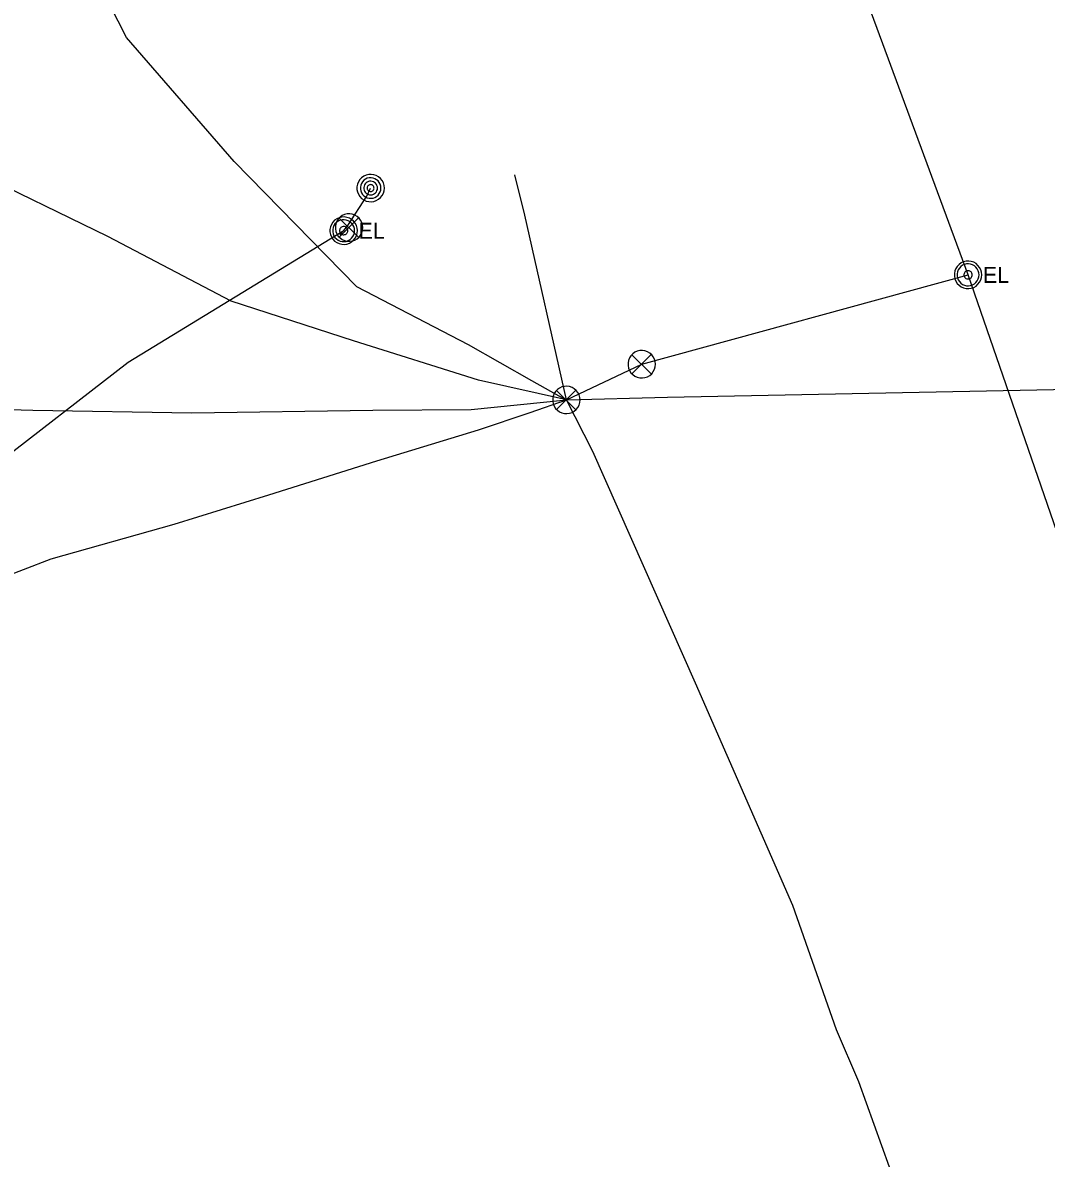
# Model space of a CAD drawing. Extents: x 600849 to 606371, y 330010 to 403088.
# Drawn here: x 603787.2 to 604033, y 349495.8 to 349768.6 of the extents above; entities that cross this region are included whole.
import ezdxf

# ---------------------------------------------------------------- set-up
doc = ezdxf.new("R2010")
doc.units = 0
for name, color, linetype in [('E_FTMS', 7, 'Continuous'), ('E_FTMS_Conduit', 7, 'Continuous'), ('E_LTG_CID', 7, 'Continuous'), ('E_MISCPROP', 7, 'Continuous'), ('E_SIG', 7, 'Continuous'), ('E_UTL_E', 7, 'Continuous'), ('E_UTL_T_UG', 7, 'Continuous')]:
    doc.layers.add(name, color=color, linetype=linetype)

msp = doc.modelspace()

# ---------------------------------------------------------------- linework, layer by layer
at = {"layer": 'E_FTMS'}
for points in [[(603868.86, 349719.43), (603868.8, 349720.05), (603868.62, 349720.66), (603868.33, 349721.21), (603867.95, 349721.71), (603867.47, 349722.12), (603866.93, 349722.43), (603866.33, 349722.64), (603865.71, 349722.73), (603865.09, 349722.7), (603864.48, 349722.55), (603863.91, 349722.29), (603863.4, 349721.92), (603862.96, 349721.47), (603862.62, 349720.94), (603862.39, 349720.36), (603862.27, 349719.74), (603862.27, 349719.12), (603862.39, 349718.5), (603862.62, 349717.92), (603862.96, 349717.39), (603863.4, 349716.94), (603863.91, 349716.57), (603864.48, 349716.31), (603865.09, 349716.16), (603865.71, 349716.13), (603866.33, 349716.22), (603866.93, 349716.43), (603867.47, 349716.74), (603867.95, 349717.15), (603868.33, 349717.65), (603868.62, 349718.2), (603868.8, 349718.81), (603868.86, 349719.43)], [(603867.82, 349721.76), (603863.21, 349717.11)], [(603863.21, 349721.72), (603867.86, 349717.06)], [(603921.05, 349678.01), (603920.99, 349678.63), (603920.81, 349679.23), (603920.52, 349679.79), (603920.14, 349680.29), (603919.66, 349680.7), (603919.12, 349681.01), (603918.53, 349681.21), (603917.9, 349681.3), (603917.28, 349681.27), (603916.67, 349681.13), (603916.1, 349680.87), (603915.59, 349680.5), (603915.15, 349680.05), (603914.81, 349679.52), (603914.58, 349678.94), (603914.46, 349678.32), (603914.46, 349677.69), (603914.58, 349677.08), (603914.81, 349676.5), (603915.15, 349675.97), (603915.59, 349675.51), (603916.1, 349675.15), (603916.67, 349674.89), (603917.28, 349674.74), (603917.9, 349674.71), (603918.53, 349674.8), (603919.12, 349675.01), (603919.66, 349675.32), (603920.14, 349675.73), (603920.52, 349676.22), (603920.81, 349676.78), (603920.99, 349677.38), (603921.05, 349678.01)], [(603920.01, 349680.34), (603915.4, 349675.69)], [(603915.4, 349680.29), (603920.05, 349675.64)]]:
    msp.add_lwpolyline(points, dxfattribs=at)
at = {"layer": 'E_FTMS_Conduit'}
for points in [[(603917.75, 349678.01), (603916.03, 349678.92), (603909.47, 349682.62), (603894.24, 349691.26), (603867.44, 349705.17), (603837.96, 349735.31), (603812.11, 349765.12), (603792, 349804.62)], [(603982.63, 349526.67), (603972.12, 349556.51), (603948.77, 349609.95), (603924.1, 349665.61), (603917.75, 349678.01), (603907.79, 349722.38), (603905.34, 349732.1)], [(603863.31, 349717.64), (603864.3, 349718.69), (603865.25, 349719.95), (603869.81, 349726.99), (603870.73, 349728.92)], [(603744.86, 349619.98), (603745.63, 349621.39), (603766.11, 349640.68), (603779.36, 349661.48), (603812.47, 349687.08), (603864.3, 349718.69)], [(603754.02, 349624.44), (603794, 349639.8), (603823.54, 349648.17), (603846.28, 349655.2), (603872.25, 349663.34), (603896.64, 349670.84), (603909.04, 349674.97), (603917.75, 349678.01)], [(604122.74, 348988.04), (604108.56, 349049.67), (604100.88, 349081.84), (604090.92, 349138.93), (604079.09, 349196.91), (604056.03, 349276.86), (604043.16, 349350.52), (604043.52, 349350.57), (604038.65, 349379.99), (604027.8, 349419.58), (604014.43, 349447.39), (603999.06, 349483.4), (603987.98, 349514.15), (603982.63, 349526.67)]]:
    msp.add_lwpolyline(points, dxfattribs=at)
at = {"layer": 'E_LTG_CID'}
for points in [[(604318.05, 348339.7), (604287.36, 348606.91), (604242.16, 348872.6), (604188.57, 349120.13), (604125.01, 349362.84), (604050.82, 349602.08), (604014.23, 349708.06), (603966.43, 349837.54), (603869.82, 350091.09), (603838.85, 350172.22), (603784.41, 350315.72), (603699.29, 350539.43), (603613.87, 350764.2), (603510.34, 351036.54), (603442.84, 351213.06), (603357.76, 351436.96)], [(603917.75, 349678.01), (603896.67, 349682.78), (603866.61, 349692.2), (603837.24, 349701.77), (603807.63, 349717.3), (603774.3, 349733.47), (603748.77, 349742.3), (603723.01, 349748.61), (603703.89, 349751.51), (603692.25, 349754.99), (603690.94, 349755.27)], [(603935.86, 349686.59), (604014.23, 349708.06)], [(603917.75, 349678.01), (603935.86, 349686.59)]]:
    msp.add_lwpolyline(points, dxfattribs=at)
at = {"layer": 'E_MISCPROP'}
for points in [[(603874.03, 349728.92), (603873.97, 349729.54), (603873.79, 349730.14), (603873.5, 349730.7), (603873.11, 349731.19), (603872.64, 349731.61), (603872.1, 349731.92), (603871.5, 349732.12), (603870.88, 349732.21), (603870.26, 349732.18), (603869.65, 349732.04), (603869.08, 349731.78), (603868.56, 349731.41), (603868.13, 349730.96), (603867.79, 349730.43), (603867.56, 349729.85), (603867.44, 349729.23), (603867.44, 349728.6), (603867.56, 349727.99), (603867.79, 349727.41), (603868.13, 349726.88), (603868.56, 349726.42), (603869.08, 349726.06), (603869.65, 349725.8), (603870.26, 349725.65), (603870.88, 349725.62), (603871.5, 349725.71), (603872.1, 349725.92), (603872.64, 349726.23), (603873.11, 349726.64), (603873.5, 349727.13), (603873.79, 349727.69), (603873.97, 349728.29), (603874.03, 349728.92)], [(603873.2, 349728.92), (603873.16, 349729.39), (603873.02, 349729.84), (603872.81, 349730.26), (603872.52, 349730.63), (603872.16, 349730.93), (603871.75, 349731.17), (603871.31, 349731.32), (603870.84, 349731.39), (603870.37, 349731.37), (603869.92, 349731.26), (603869.49, 349731.06), (603869.1, 349730.79), (603868.78, 349730.45), (603868.53, 349730.05), (603868.35, 349729.61), (603868.26, 349729.15), (603868.26, 349728.68), (603868.35, 349728.22), (603868.53, 349727.78), (603868.78, 349727.39), (603869.1, 349727.05), (603869.49, 349726.77), (603869.92, 349726.58), (603870.37, 349726.47), (603870.84, 349726.45), (603871.31, 349726.51), (603871.75, 349726.67), (603872.16, 349726.9), (603872.52, 349727.21), (603872.81, 349727.58), (603873.02, 349728), (603873.16, 349728.45), (603873.2, 349728.92)], [(603872.38, 349728.92), (603872.35, 349729.23), (603872.26, 349729.53), (603872.11, 349729.81), (603871.92, 349730.06), (603871.68, 349730.26), (603871.41, 349730.42), (603871.11, 349730.52), (603870.8, 349730.57), (603870.49, 349730.55), (603870.19, 349730.48), (603869.9, 349730.35), (603869.65, 349730.16), (603869.43, 349729.94), (603869.26, 349729.67), (603869.14, 349729.38), (603869.08, 349729.07), (603869.08, 349728.76), (603869.14, 349728.45), (603869.26, 349728.16), (603869.43, 349727.9), (603869.65, 349727.67), (603869.9, 349727.49), (603870.19, 349727.36), (603870.49, 349727.28), (603870.8, 349727.27), (603871.11, 349727.31), (603871.41, 349727.42), (603871.68, 349727.57), (603871.92, 349727.78), (603872.11, 349728.03), (603872.26, 349728.3), (603872.35, 349728.61), (603872.38, 349728.92)], [(603871.55, 349728.92), (603871.54, 349729.07), (603871.49, 349729.22), (603871.42, 349729.36), (603871.32, 349729.49), (603871.2, 349729.59), (603871.07, 349729.67), (603870.92, 349729.72), (603870.76, 349729.74), (603870.61, 349729.73), (603870.46, 349729.7), (603870.31, 349729.63), (603870.19, 349729.54), (603870.08, 349729.43), (603869.99, 349729.3), (603869.93, 349729.15), (603869.9, 349729), (603869.9, 349728.84), (603869.93, 349728.68), (603869.99, 349728.54), (603870.08, 349728.41), (603870.19, 349728.29), (603870.31, 349728.2), (603870.46, 349728.14), (603870.61, 349728.1), (603870.76, 349728.09), (603870.92, 349728.12), (603871.07, 349728.17), (603871.2, 349728.25), (603871.32, 349728.35), (603871.42, 349728.47), (603871.49, 349728.61), (603871.54, 349728.76), (603871.55, 349728.92)]]:
    msp.add_lwpolyline(points, dxfattribs=at)
at = {"layer": 'E_SIG'}
for points in [[(603939.16, 349686.59), (603939.1, 349687.21), (603938.92, 349687.81), (603938.63, 349688.37), (603938.24, 349688.87), (603937.77, 349689.28), (603937.23, 349689.59), (603936.63, 349689.79), (603936.01, 349689.88), (603935.39, 349689.85), (603934.78, 349689.71), (603934.21, 349689.45), (603933.7, 349689.08), (603933.26, 349688.63), (603932.92, 349688.1), (603932.69, 349687.52), (603932.57, 349686.9), (603932.57, 349686.27), (603932.69, 349685.66), (603932.92, 349685.08), (603933.26, 349684.55), (603933.7, 349684.09), (603934.21, 349683.73), (603934.78, 349683.47), (603935.39, 349683.32), (603936.01, 349683.29), (603936.63, 349683.38), (603937.23, 349683.59), (603937.77, 349683.9), (603938.24, 349684.31), (603938.63, 349684.8), (603938.92, 349685.36), (603939.1, 349685.96), (603939.16, 349686.59)], [(603938.12, 349688.92), (603933.51, 349684.27)], [(603933.51, 349688.87), (603938.16, 349684.22)]]:
    msp.add_lwpolyline(points, dxfattribs=at)
at = {"layer": 'E_UTL_E'}
for points in [[(603867.55, 349718.68), (603867.49, 349719.3), (603867.31, 349719.9), (603867.02, 349720.46), (603866.64, 349720.95), (603866.16, 349721.37), (603865.62, 349721.68), (603865.02, 349721.88), (603864.4, 349721.97), (603863.78, 349721.94), (603863.17, 349721.8), (603862.6, 349721.54), (603862.09, 349721.17), (603861.65, 349720.72), (603861.31, 349720.19), (603861.08, 349719.61), (603860.96, 349718.99), (603860.96, 349718.36), (603861.08, 349717.75), (603861.31, 349717.17), (603861.65, 349716.64), (603862.09, 349716.18), (603862.6, 349715.82), (603863.17, 349715.56), (603863.78, 349715.41), (603864.4, 349715.38), (603865.02, 349715.47), (603865.62, 349715.68), (603866.16, 349715.99), (603866.64, 349716.4), (603867.02, 349716.89), (603867.31, 349717.45), (603867.49, 349718.05), (603867.55, 349718.68)], [(603867.55, 349718.68), (603867.49, 349719.3), (603867.31, 349719.9), (603867.02, 349720.46), (603866.64, 349720.95), (603866.16, 349721.37), (603865.62, 349721.68), (603865.02, 349721.88), (603864.4, 349721.97), (603863.78, 349721.94), (603863.17, 349721.8), (603862.6, 349721.54), (603862.09, 349721.17), (603861.65, 349720.72), (603861.31, 349720.19), (603861.08, 349719.61), (603860.96, 349718.99), (603860.96, 349718.36), (603861.08, 349717.75), (603861.31, 349717.17), (603861.65, 349716.64), (603862.09, 349716.18), (603862.6, 349715.82), (603863.17, 349715.56), (603863.78, 349715.41), (603864.4, 349715.38), (603865.02, 349715.47), (603865.62, 349715.68), (603866.16, 349715.99), (603866.64, 349716.4), (603867.02, 349716.89), (603867.31, 349717.45), (603867.49, 349718.05), (603867.55, 349718.68)], [(603866.89, 349718.68), (603866.84, 349719.18), (603866.7, 349719.66), (603866.47, 349720.1), (603866.16, 349720.5), (603865.78, 349720.83), (603865.34, 349721.08), (603864.87, 349721.24), (603864.37, 349721.31), (603863.87, 349721.29), (603863.38, 349721.17), (603862.93, 349720.96), (603862.52, 349720.67), (603862.17, 349720.31), (603861.9, 349719.89), (603861.71, 349719.42), (603861.62, 349718.93), (603861.62, 349718.43), (603861.71, 349717.93), (603861.9, 349717.47), (603862.17, 349717.05), (603862.52, 349716.68), (603862.93, 349716.39), (603863.38, 349716.18), (603863.87, 349716.06), (603864.37, 349716.04), (603864.87, 349716.11), (603865.34, 349716.28), (603865.78, 349716.53), (603866.16, 349716.86), (603866.47, 349717.25), (603866.7, 349717.7), (603866.84, 349718.18), (603866.89, 349718.68)], [(603866.89, 349718.68), (603866.84, 349719.18), (603866.7, 349719.66), (603866.47, 349720.1), (603866.16, 349720.5), (603865.78, 349720.83), (603865.34, 349721.08), (603864.87, 349721.24), (603864.37, 349721.31), (603863.87, 349721.29), (603863.38, 349721.17), (603862.93, 349720.96), (603862.52, 349720.67), (603862.17, 349720.31), (603861.9, 349719.89), (603861.71, 349719.42), (603861.62, 349718.93), (603861.62, 349718.43), (603861.71, 349717.93), (603861.9, 349717.47), (603862.17, 349717.05), (603862.52, 349716.68), (603862.93, 349716.39), (603863.38, 349716.18), (603863.87, 349716.06), (603864.37, 349716.04), (603864.87, 349716.11), (603865.34, 349716.28), (603865.78, 349716.53), (603866.16, 349716.86), (603866.47, 349717.25), (603866.7, 349717.7), (603866.84, 349718.18), (603866.89, 349718.68)], [(603865.24, 349718.68), (603865.22, 349718.87), (603865.17, 349719.05), (603865.08, 349719.21), (603864.96, 349719.36), (603864.82, 349719.48), (603864.66, 349719.58), (603864.48, 349719.64), (603864.29, 349719.67), (603864.11, 349719.66), (603863.92, 349719.61), (603863.75, 349719.54), (603863.6, 349719.43), (603863.47, 349719.29), (603863.37, 349719.13), (603863.3, 349718.96), (603863.26, 349718.77), (603863.26, 349718.58), (603863.3, 349718.4), (603863.37, 349718.22), (603863.47, 349718.07), (603863.6, 349717.93), (603863.75, 349717.82), (603863.92, 349717.74), (603864.11, 349717.7), (603864.29, 349717.69), (603864.48, 349717.72), (603864.66, 349717.78), (603864.82, 349717.87), (603864.96, 349717.99), (603865.08, 349718.14), (603865.17, 349718.31), (603865.22, 349718.49), (603865.24, 349718.68)], [(603865.24, 349718.68), (603865.22, 349718.87), (603865.17, 349719.05), (603865.08, 349719.21), (603864.96, 349719.36), (603864.82, 349719.48), (603864.66, 349719.58), (603864.48, 349719.64), (603864.29, 349719.67), (603864.11, 349719.66), (603863.92, 349719.61), (603863.75, 349719.54), (603863.6, 349719.43), (603863.47, 349719.29), (603863.37, 349719.13), (603863.3, 349718.96), (603863.26, 349718.77), (603863.26, 349718.58), (603863.3, 349718.4), (603863.37, 349718.22), (603863.47, 349718.07), (603863.6, 349717.93), (603863.75, 349717.82), (603863.92, 349717.74), (603864.11, 349717.7), (603864.29, 349717.69), (603864.48, 349717.72), (603864.66, 349717.78), (603864.82, 349717.87), (603864.96, 349717.99), (603865.08, 349718.14), (603865.17, 349718.31), (603865.22, 349718.49), (603865.24, 349718.68)], [(604017.53, 349708.06), (604017.47, 349708.69), (604017.3, 349709.29), (604017.01, 349709.85), (604016.62, 349710.34), (604016.15, 349710.75), (604015.6, 349711.07), (604015.01, 349711.27), (604014.39, 349711.36), (604013.76, 349711.33), (604013.15, 349711.18), (604012.58, 349710.92), (604012.07, 349710.56), (604011.64, 349710.1), (604011.3, 349709.58), (604011.07, 349708.99), (604010.95, 349708.38), (604010.95, 349707.75), (604011.07, 349707.13), (604011.3, 349706.55), (604011.64, 349706.02), (604012.07, 349705.57), (604012.58, 349705.21), (604013.15, 349704.95), (604013.76, 349704.8), (604014.39, 349704.77), (604015.01, 349704.86), (604015.6, 349705.06), (604016.15, 349705.38), (604016.62, 349705.79), (604017.01, 349706.28), (604017.3, 349706.84), (604017.47, 349707.44), (604017.53, 349708.06)], [(604017.53, 349708.06), (604017.47, 349708.69), (604017.3, 349709.29), (604017.01, 349709.85), (604016.62, 349710.34), (604016.15, 349710.75), (604015.6, 349711.07), (604015.01, 349711.27), (604014.39, 349711.36), (604013.76, 349711.33), (604013.15, 349711.18), (604012.58, 349710.92), (604012.07, 349710.56), (604011.64, 349710.1), (604011.3, 349709.58), (604011.07, 349708.99), (604010.95, 349708.38), (604010.95, 349707.75), (604011.07, 349707.13), (604011.3, 349706.55), (604011.64, 349706.02), (604012.07, 349705.57), (604012.58, 349705.21), (604013.15, 349704.95), (604013.76, 349704.8), (604014.39, 349704.77), (604015.01, 349704.86), (604015.6, 349705.06), (604016.15, 349705.38), (604016.62, 349705.79), (604017.01, 349706.28), (604017.3, 349706.84), (604017.47, 349707.44), (604017.53, 349708.06)], [(604016.87, 349708.06), (604016.82, 349708.56), (604016.68, 349709.04), (604016.45, 349709.49), (604016.14, 349709.89), (604015.76, 349710.21), (604015.33, 349710.47), (604014.86, 349710.63), (604014.36, 349710.7), (604013.86, 349710.68), (604013.37, 349710.56), (604012.91, 349710.35), (604012.5, 349710.06), (604012.16, 349709.7), (604011.89, 349709.27), (604011.7, 349708.81), (604011.6, 349708.31), (604011.6, 349707.81), (604011.7, 349707.32), (604011.89, 349706.85), (604012.16, 349706.43), (604012.5, 349706.07), (604012.91, 349705.78), (604013.37, 349705.57), (604013.86, 349705.45), (604014.36, 349705.43), (604014.86, 349705.5), (604015.33, 349705.66), (604015.76, 349705.91), (604016.14, 349706.24), (604016.45, 349706.64), (604016.68, 349707.08), (604016.82, 349707.56), (604016.87, 349708.06)], [(604016.87, 349708.06), (604016.82, 349708.56), (604016.68, 349709.04), (604016.45, 349709.49), (604016.14, 349709.89), (604015.76, 349710.21), (604015.33, 349710.47), (604014.86, 349710.63), (604014.36, 349710.7), (604013.86, 349710.68), (604013.37, 349710.56), (604012.91, 349710.35), (604012.5, 349710.06), (604012.16, 349709.7), (604011.89, 349709.27), (604011.7, 349708.81), (604011.6, 349708.31), (604011.6, 349707.81), (604011.7, 349707.32), (604011.89, 349706.85), (604012.16, 349706.43), (604012.5, 349706.07), (604012.91, 349705.78), (604013.37, 349705.57), (604013.86, 349705.45), (604014.36, 349705.43), (604014.86, 349705.5), (604015.33, 349705.66), (604015.76, 349705.91), (604016.14, 349706.24), (604016.45, 349706.64), (604016.68, 349707.08), (604016.82, 349707.56), (604016.87, 349708.06)], [(604015.22, 349708.06), (604015.2, 349708.25), (604015.15, 349708.43), (604015.07, 349708.6), (604014.95, 349708.75), (604014.81, 349708.87), (604014.64, 349708.96), (604014.47, 349709.03), (604014.28, 349709.05), (604014.09, 349709.04), (604013.91, 349709), (604013.74, 349708.92), (604013.58, 349708.81), (604013.45, 349708.68), (604013.35, 349708.52), (604013.28, 349708.34), (604013.25, 349708.16), (604013.25, 349707.97), (604013.28, 349707.78), (604013.35, 349707.61), (604013.45, 349707.45), (604013.58, 349707.32), (604013.74, 349707.21), (604013.91, 349707.13), (604014.09, 349707.08), (604014.28, 349707.07), (604014.47, 349707.1), (604014.64, 349707.16), (604014.81, 349707.26), (604014.95, 349707.38), (604015.07, 349707.53), (604015.15, 349707.7), (604015.2, 349707.88), (604015.22, 349708.06)], [(604015.22, 349708.06), (604015.2, 349708.25), (604015.15, 349708.43), (604015.07, 349708.6), (604014.95, 349708.75), (604014.81, 349708.87), (604014.64, 349708.96), (604014.47, 349709.03), (604014.28, 349709.05), (604014.09, 349709.04), (604013.91, 349709), (604013.74, 349708.92), (604013.58, 349708.81), (604013.45, 349708.68), (604013.35, 349708.52), (604013.28, 349708.34), (604013.25, 349708.16), (604013.25, 349707.97), (604013.28, 349707.78), (604013.35, 349707.61), (604013.45, 349707.45), (604013.58, 349707.32), (604013.74, 349707.21), (604013.91, 349707.13), (604014.09, 349707.08), (604014.28, 349707.07), (604014.47, 349707.1), (604014.64, 349707.16), (604014.81, 349707.26), (604014.95, 349707.38), (604015.07, 349707.53), (604015.15, 349707.7), (604015.2, 349707.88), (604015.22, 349708.06)]]:
    msp.add_lwpolyline(points, dxfattribs=at)
at = {"layer": 'E_UTL_T_UG'}
msp.add_lwpolyline([(603645.71, 349671.24), (603724.65, 349677.37), (603789.57, 349675.58), (603827.82, 349674.94), (603871.28, 349675.53), (603894.87, 349675.71), (603917.75, 349678.01), (603942.05, 349678.68), (604107.36, 349681.99), (604145.26, 349681.23), (604210.26, 349682.16), (604241.64, 349682.56), (604267.28, 349684.76), (604298.14, 349688.92), (604320.51, 349691.88), (604327.72, 349692.91)], dxfattribs=at)

# ---------------------------------------------------------------- texts
at = {"layer": 'E_UTL_E'}
for p in [(603867.81, 349716.73), (603867.81, 349716.73), (604017.8, 349706.12), (604017.8, 349706.12)]:
    msp.add_text('EL', height=3.849, dxfattribs=at).set_placement(p)

doc.saveas('drawing.dxf')
